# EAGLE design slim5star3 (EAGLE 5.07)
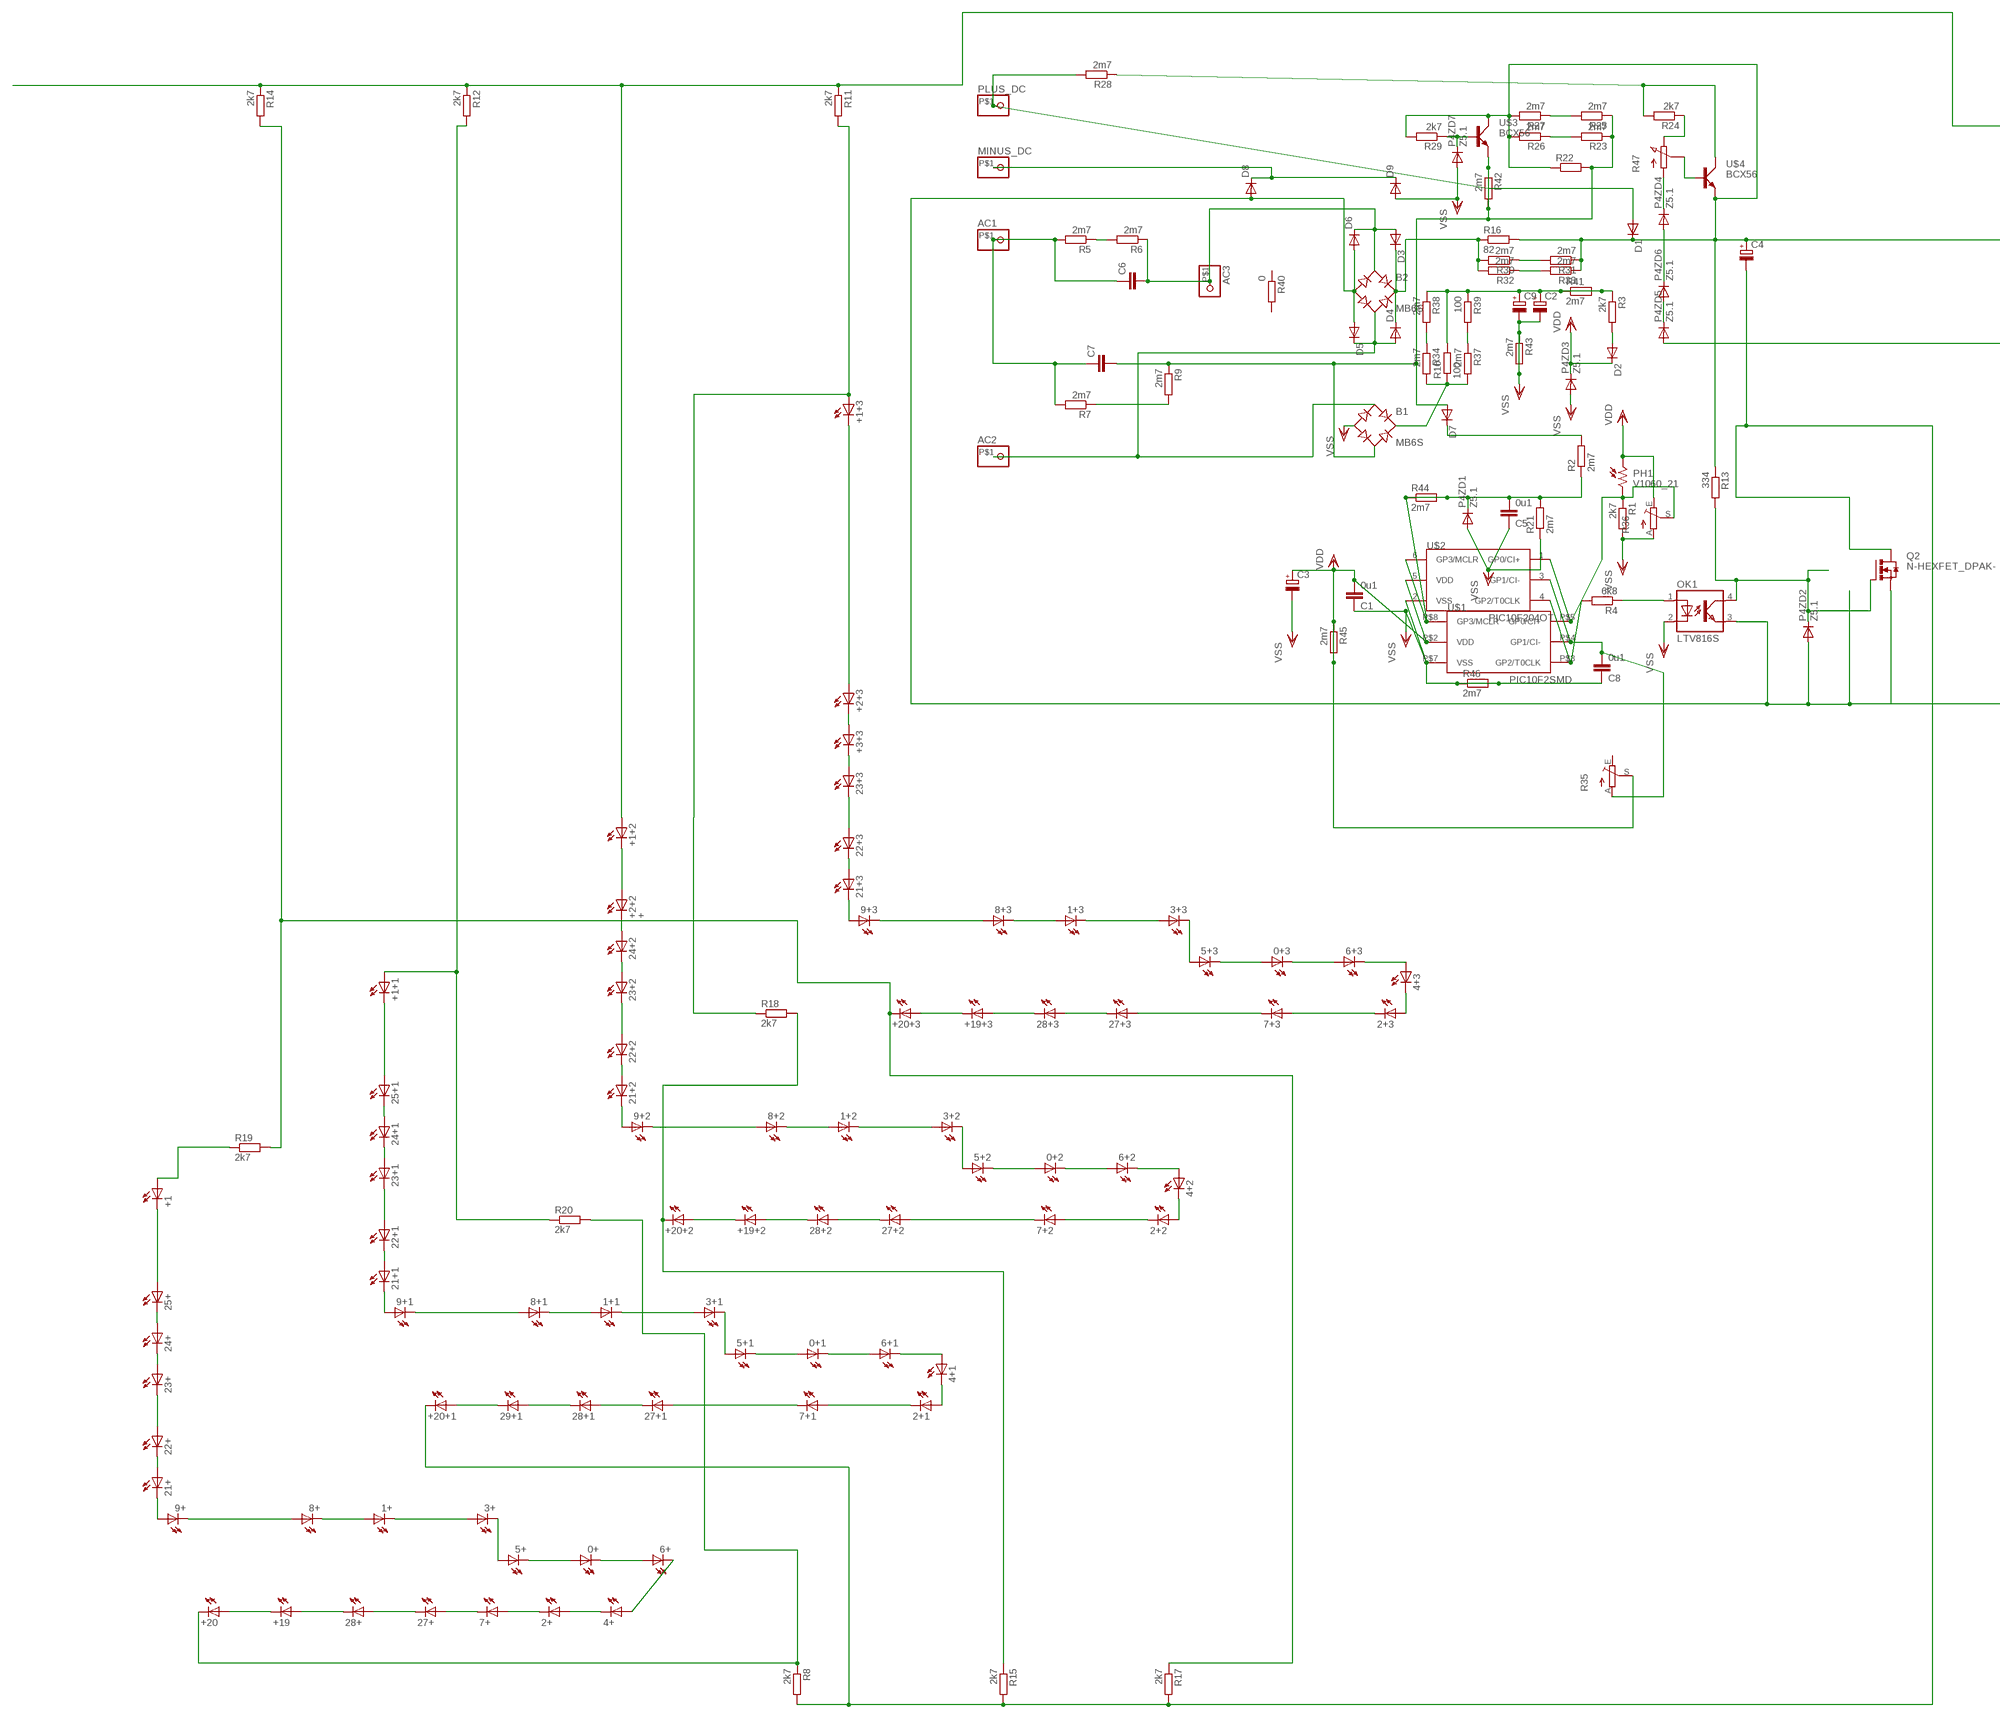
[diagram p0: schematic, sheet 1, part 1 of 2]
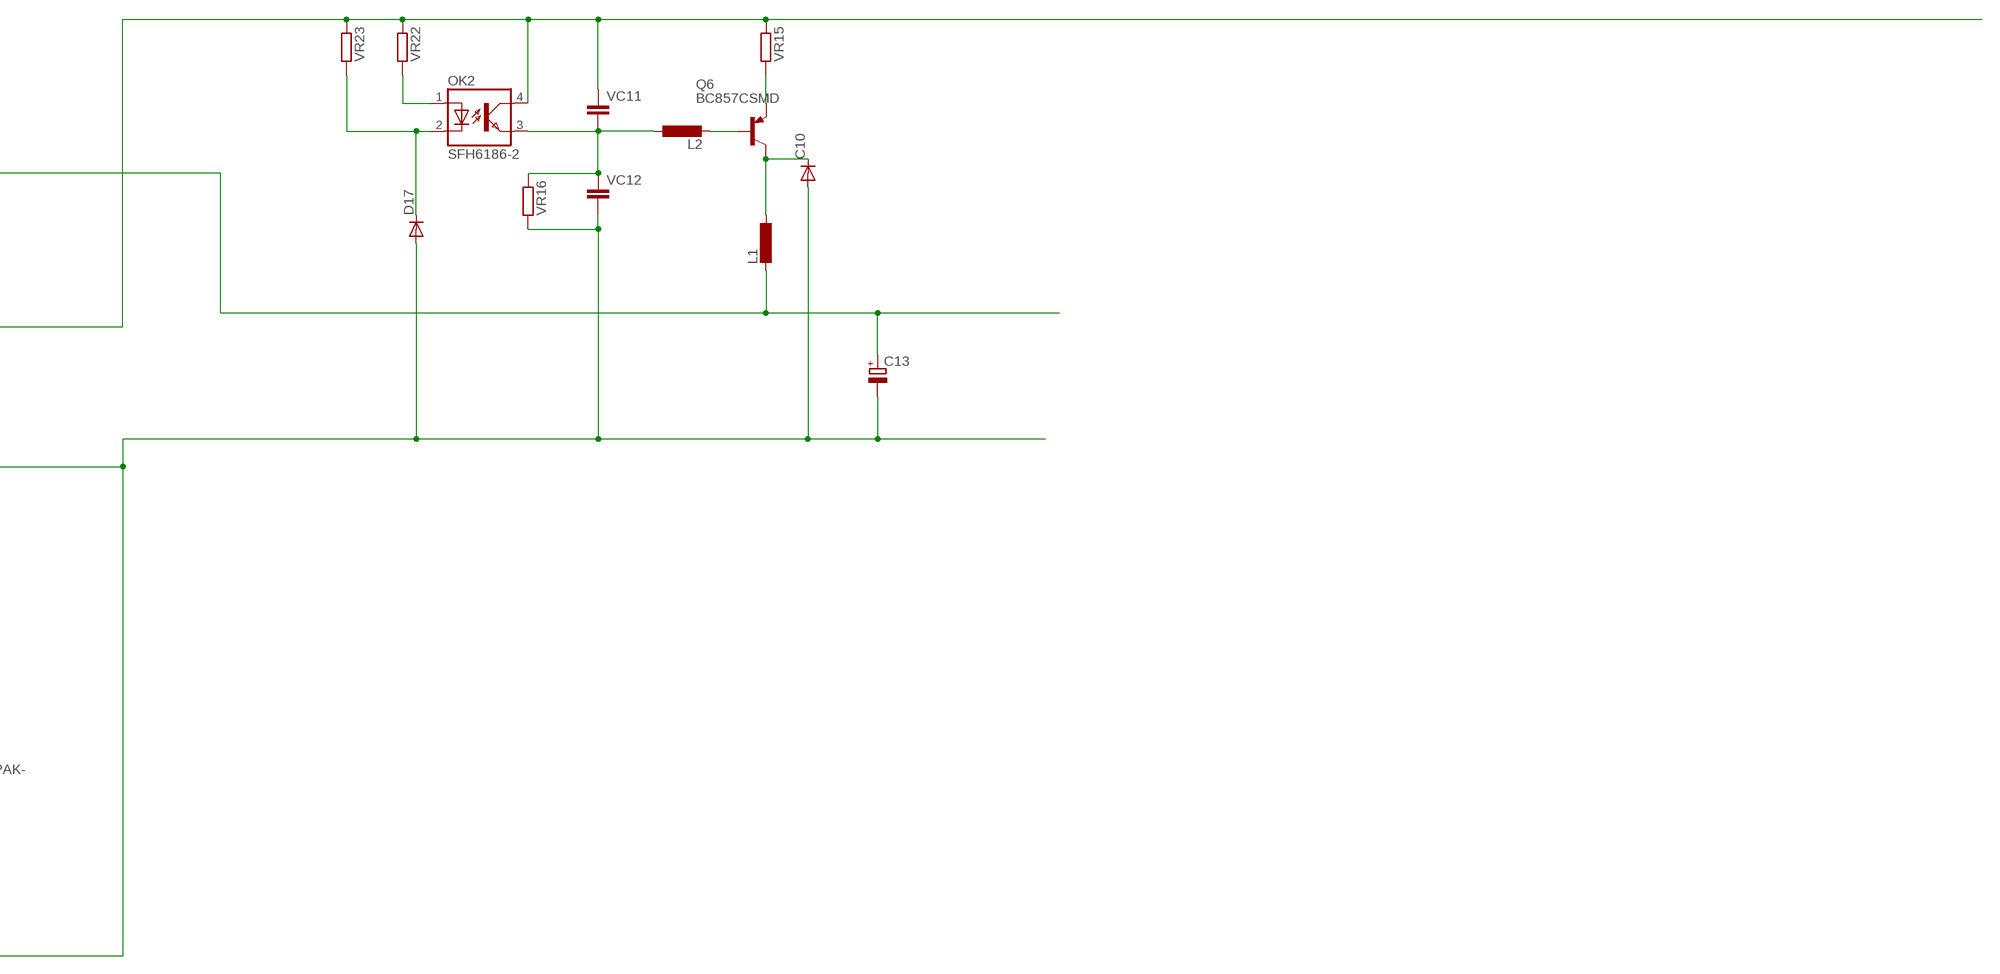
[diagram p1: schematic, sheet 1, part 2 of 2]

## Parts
0+  LED1210  [1210]
0+1  LED1210  [1210]
0+2  LED1210  [1210]
0+3  LED1210  [1210]
1+  LED1210  [1210]
1+1  LED1210  [1210]
1+2  LED1210  [1210]
1+3  LED1210  [1210]
2+  LED1210  [1210]
2+1  LED1210  [1210]
2+2  LED1210  [1210]
2+3  LED1210  [1210]
3+  LED1210  [1210]
3+1  LED1210  [1210]
3+2  LED1210  [1210]
3+3  LED1210  [1210]
4+  LED1210  [1210]
4+1  LED1210  [1210]
4+2  LED1210  [1210]
4+3  LED1210  [1210]
5+  LED1210  [1210]
5+1  LED1210  [1210]
5+2  LED1210  [1210]
5+3  LED1210  [1210]
6+  LED1210  [1210]
6+1  LED1210  [1210]
6+2  LED1210  [1210]
6+3  LED1210  [1210]
7+  LED1210  [1210]
7+1  LED1210  [1210]
7+2  LED1210  [1210]
7+3  LED1210  [1210]
8+  LED1210  [1210]
8+1  LED1210  [1210]
8+2  LED1210  [1210]
8+3  LED1210  [1210]
9+  LED1210  [1210]
9+1  LED1210  [1210]
9+2  LED1210  [1210]
9+3  LED1210  [1210]
21+  LED1210  [1210]
21+1  LED1210  [1210]
21+2  LED1210  [1210]
21+3  LED1210  [1210]
22+  LED1210  [1210]
22+1  LED1210  [1210]
22+2  LED1210  [1210]
22+3  LED1210  [1210]
23+  LED1210  [1210]
23+1  LED1210  [1210]
23+2  LED1210  [1210]
23+3  LED1210  [1210]
24+  LED1210  [1210]
24+1  LED1210  [1210]
24+2  LED1210  [1210]
25+  LED1210  [1210]
25+1  LED1210  [1210]
27+  LED1210  [1210]
27+1  LED1210  [1210]
27+2  LED1210  [1210]
27+3  LED1210  [1210]
28+  LED1210  [1210]
28+1  LED1210  [1210]
28+2  LED1210  [1210]
28+3  LED1210  [1210]
29+1  LED1210  [1210]
+1  LED1210  [1210]
+1+1  LED1210  [1210]
+1+2  LED1210  [1210]
+1+3  LED1210  [1210]
+2+2  +  LED1210  [1210]
+2+3  LED1210  [1210]
+3+3  LED1210  [1210]
+19  LED1210  [1210]
+19+2  LED1210  [1210]
+19+3  LED1210  [1210]
+20  LED1210  [1210]
+20+1  LED1210  [1210]
+20+2  LED1210  [1210]
+20+3  LED1210  [1210]
AC1  PINHD-1X1SMD  [SMD1X1]
AC2  PINHD-1X1SMD  [SMD1X1]
AC3  PINHD-1X1SMD  [SMD1X1]
B1  MB6S  [SOIC-4]
B2  MB6S  [SOIC-4]
C1  0u1  C-EUC1206  [C1206]
C2  CPOL-EUE2.5-4V  [E2,5RE]
C3  CPOL-EUE  [PANASONIC_E]
C4  CPOL-EUSANYO_SMD_F12  [SANYO-OSCON_SMD_F12]
C5  0u1  C-EUC1206  [C1206]
C6  C-EUSMD200  [SMD200]
C7  C-EUSMD100  [SMD100]
C8  0u1  C-EUC1206  [C1206]
C9  CPOL-EUE  [PANASONIC_E]
C10  DIODE-SMB  [SMB]
C13  CPOL-EUSMCC  [SMC_C]
D1  DIODE-SMB  [SMB]
D2  DIODE-MINIMELF  [MINIMELF]
D3  DIODE-SMB  [SMB]
D4  DIODE-SMB  [SMB]
D5  DIODE-SMB  [SMB]
D6  DIODE-SMB  [SMB]
D7  DIODE-MINIMELF  [MINIMELF]
D8  DIODE-SMB  [SMB]
D9  DIODE-SMB  [SMB]
D17  DIODE-MINIMELF  [MINIMELF]
L1  L-EUL5650M  [L5650M]
L2  L-EUL5650M  [L5650M]
MINUS_DC  PINHD-1X1SMD  [SMD1X1]
OK1  LTV816S  [SMD4]
OK2  SFH6186-2  [SMD4]
P4ZD1  Z5.1  DIODE-MINIMELF  [MINIMELF]
P4ZD2  Z5.1  DIODE-MINIMELF  [MINIMELF]
P4ZD3  Z5.1  DIODE-MINIMELF  [MINIMELF]
P4ZD4  Z5.1  DIODE-MINIMELF  [MINIMELF]
P4ZD5  Z5.1  DIODE-MINIMELF  [MINIMELF]
P4ZD6  Z5.1  DIODE-MINIMELF  [MINIMELF]
P4ZD7  Z5.1  DIODE-MINIMELF  [MINIMELF]
PH1  V1060_21  [TO-5_V10]
PLUS_DC  PINHD-1X1SMD  [SMD1X1]
Q2  N-HEXFET_DPAK-  [TO252]
Q6  BC857CSMD  [SOT23-BEC]
R1  2k7  R-EU_R1206  [R1206]
R2  2m7  R-EU_R2010  [R2010]
R3  2k7  R-EU_R1206  [R1206]
R4  6k8  R-EU_R1206  [R1206]
R5  2m7  R-EU_R1210  [R1210]
R6  2m7  R-EU_R1210  [R1210]
R7  2m7  R-EU_R1210  [R1210]
R8  2k7  R-EU_R0402  [R0402]
R9  2m7  R-EU_R1210  [R1210]
R10  100  R-EU_SMD15  [SMDCARB15]
R11  2k7  R-EU_R0402  [R0402]
R12  2k7  R-EU_R0402  [R0402]
R13  334  R-EU_R1206  [R1206]
R14  2k7  R-EU_R0402  [R0402]
R15  2k7  R-EU_R0402  [R0402]
R16  82  R-EU_SMD15  [SMDCARB15]
R17  2k7  R-EU_R0402  [R0402]
R18  2k7  R-EU_R0402  [R0402]
R19  2k7  R-EU_R0402  [R0402]
R20  2k7  R-EU_R0402  [R0402]
R21  2m7  R-EU_R1206  [R1206]
R22  R-EU_SMD15  [SMDCARB15]
R23  2m7  R-EU_R1210  [R1210]
R24  2k7  R-EU_R1206  [R1206]
R25  2m7  R-EU_R1210  [R1210]
R26  2m7  R-EU_R1210  [R1210]
R27  2m7  R-EU_R1210  [R1210]
R28  2m7  R-EU_R1210  [R1210]
R29  2k7  R-EU_R1206  [R1206]
R30  2m7  R-EU_R1210  [R1210]
R31  2m7  R-EU_R1210  [R1210]
R32  2m7  R-EU_R1210  [R1210]
R33  2m7  R-EU_R1210  [R1210]
R34  2m7  R-EU_R1210  [R1210]
R35  TRIM_EU-LI10  [LI10]
R36  TRIM_EU-LI15  [LI15]
R37  2m7  R-EU_R1210  [R1210]
R38  2m7  R-EU_R1210  [R1210]
R39  100  R-EU_R1210  [R1210]
R40  0  R-EU_R2010  [R2010]
R41  2m7  R-EU_R2010  [R2010]
R42  2m7  R-EU_R2010  [R2010]
R43  2m7  R-EU_R2010  [R2010]
R44  2m7  R-EU_R2010  [R2010]
R45  2m7  R-EU_R2010  [R2010]
R46  2m7  R-EU_R2010  [R2010]
R47  PC25  [PC25]
U$1  PIC10F2SMD  [DIL8SMD]
U$2  PIC10F204OT  [SOT23-6]
U$3  BCX56  [SOT223]
U$4  BCX56  [SOT223]
VC11  C-EUC0805  [C0805]
VC12  C-EUC0805  [C0805]
VR15  R-EU_R1210  [R1210]
VR16  R-EU_R1206  [R1206]
VR22  R-EU_R1206  [R1206]
VR23  R-EU_R1206  [R1206]

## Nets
AC1: AC1.P$1 C6.P$1 C7.P$1 R5.2 R7.2
AC2: AC2.P$1 B1.~1(AC1) B2.~2(AC2) D4.A D5.C
BATT-: B2.- C10.A C13.- D5.A D6.A D8.A D17.A OK1.3(EMIT) P4ZD2.A P4ZD5.A Q2.2(S) VC12.2 VR16.2
CBIG: AC3.P$1 B2.~1(AC1) C6.P$2 D3.A D6.C R6.1
CSMALL: B1.~2(AC2) C7.P$2 D7.A R9.1 R22.P$2 R23.1 R25.1 R42.1 R42.2 U$3.1(E)
D+: +1+2.P$1(A) C13.+ L1.2 R11.1 R12.1 R14.1
MI-: D8.C D9.C MINUS_DC.P$1
MINUS: +20+1.P$2(C) C4.- Q2.3(D) R8.2 R15.2 R17.2
N$1: +1+3.P$1(A) R11.2 R18.1
N$2: +1+1.P$1(A) R12.2 R20.1
N$4: +1.P$1(A) R19.1
N$5: D7.C R2.2
N$6: 8+.P$1(A) 9+.P$2(C)
N$7: +19.P$2(C) +20.P$1(A)
N$8: 28+.P$2(C) +19.P$1(A)
N$9: 27+.P$2(C) 28+.P$1(A)
N$10: 29+1.P$2(C) +20+1.P$1(A)
N$11: 28+1.P$2(C) 29+1.P$1(A)
N$12: 2+.P$2(C) 7+.P$1(A)
N$13: 7+.P$2(C) 27+.P$1(A)
N$14: 2+.P$1(A) 4+.P$2(C)
N$15: 4+.P$1(A) 6+.P$2(C)
N$16: 0+.P$2(C) 6+.P$1(A)
N$17: 0+.P$1(A) 5+.P$2(C)
N$18: 3+.P$2(C) 5+.P$1(A)
N$19: 1+.P$2(C) 3+.P$1(A)
N$20: 1+.P$1(A) 8+.P$2(C)
N$21: 27+1.P$2(C) 28+1.P$1(A)
N$22: 2+1.P$1(A) 4+1.P$2(C)
N$23: 9+.P$1(A) 21+.P$2(C)
N$24: 21+.P$1(A) 22+.P$2(C)
N$25: 22+.P$1(A) 23+.P$2(C)
N$26: 24+.P$1(A) 25+.P$2(C)
N$27: 25+.P$1(A) +1.P$2(C)
N$28: 23+.P$1(A) 24+.P$2(C)
N$29: 4+1.P$1(A) 6+1.P$2(C)
N$30: 0+1.P$2(C) 6+1.P$1(A)
N$31: 0+1.P$1(A) 5+1.P$2(C)
N$32: 3+1.P$2(C) 5+1.P$1(A)
N$33: 1+1.P$2(C) 3+1.P$1(A)
N$34: 1+1.P$1(A) 8+1.P$2(C)
N$35: 9+1.P$1(A) 21+1.P$2(C)
N$36: 21+1.P$1(A) 22+1.P$2(C)
N$37: 22+1.P$1(A) 23+1.P$2(C)
N$38: 25+1.P$1(A) +1+1.P$2(C)
N$39: 24+1.P$1(A) 25+1.P$2(C)
N$40: 23+1.P$1(A) 24+1.P$2(C)
N$41: 2+1.P$2(C) 7+1.P$1(A)
N$42: 7+1.P$2(C) 27+1.P$1(A)
N$43: 8+1.P$1(A) 9+1.P$2(C)
N$45: +20+3.P$2(C) R14.2 R17.1 R19.2
N$46: +19+2.P$2(C) +20+2.P$1(A)
N$47: 28+2.P$2(C) +19+2.P$1(A)
N$48: 27+2.P$2(C) 28+2.P$1(A)
N$49: 2+2.P$1(A) 4+2.P$2(C)
N$50: 4+2.P$1(A) 6+2.P$2(C)
N$51: 0+2.P$2(C) 6+2.P$1(A)
N$52: 0+2.P$1(A) 5+2.P$2(C)
N$53: 3+2.P$2(C) 5+2.P$1(A)
N$54: 1+2.P$2(C) 3+2.P$1(A)
N$55: 1+2.P$1(A) 8+2.P$2(C)
N$56: 9+2.P$1(A) 21+2.P$2(C)
N$57: 21+2.P$1(A) 22+2.P$2(C)
N$58: 22+2.P$1(A) 23+2.P$2(C)
N$59: +1+2.P$2(C) +2+2.P$1(A)
N$60: 24+2.P$1(A) +2+2.P$2(C)
N$61: 23+2.P$1(A) 24+2.P$2(C)
N$62: 2+2.P$2(C) 7+2.P$1(A)
N$63: 7+2.P$2(C) 27+2.P$1(A)
N$64: 8+2.P$1(A) 9+2.P$2(C)
N$65: +20+2.P$2(C) R15.1 R18.2
N$66: +20.P$2(C) R8.1 R20.2
N$67: +19+3.P$2(C) +20+3.P$1(A)
N$68: 28+3.P$2(C) +19+3.P$1(A)
N$69: 27+3.P$2(C) 28+3.P$1(A)
N$70: 2+3.P$1(A) 4+3.P$2(C)
N$71: 4+3.P$1(A) 6+3.P$2(C)
N$72: 0+3.P$2(C) 6+3.P$1(A)
N$73: 0+3.P$1(A) 5+3.P$2(C)
N$74: 3+3.P$2(C) 5+3.P$1(A)
N$75: 1+3.P$2(C) 3+3.P$1(A)
N$76: 1+3.P$1(A) 8+3.P$2(C)
N$77: 9+3.P$1(A) 21+3.P$2(C)
N$78: 21+3.P$1(A) 22+3.P$2(C)
N$79: 22+3.P$1(A) 23+3.P$2(C)
N$80: +1+3.P$2(C) +2+3.P$1(A)
N$81: +2+3.P$2(C) +3+3.P$1(A)
N$82: 23+3.P$1(A) +3+3.P$2(C)
N$83: 2+3.P$2(C) 7+3.P$1(A)
N$84: 7+3.P$2(C) 27+3.P$1(A)
N$85: 8+3.P$1(A) 9+3.P$2(C)
N$86: C5.2 P4ZD1.C R2.1 R21.2 R44.1 R44.2 U$1.P$8(GP3/MCLR) U$2.6(GP3/MCLR)
N$87: OK1.1(A) R4.1
N$88: PH1.2 R1.1 R36.S U$1.P$5(GP0/CI+) U$2.1(GP0/CI+)
N$89: R5.1 R6.2
N$90: R7.1 R9.2
N$91: B2.+ D3.C D4.C R16.P$1 R30.2 R32.2
N$92: D2.A R3.2
N$94: OK1.4(COL) P4ZD2.C Q2.1(G) R13.2
N$95: R4.2 U$1.P$3(GP2/T0CLK) U$2.4(GP2/T0CLK)
N$96: R24.2 R28.1 U$4.2(C)
N$97: R47.S U$4.3(B)
N$98: D1.A PLUS_DC.P$1 R28.2
N$99: R23.2 R26.1
N$100: R25.2 R27.1
N$101: C2.+ C9.+ R3.1 R10.P$2 R38.1 R39.1 R41.1 R41.2
N$102: C8.2 R35.A U$1.P$4(GP1/CI-) U$2.3(GP1/CI-)
N$103: P4ZD5.C P4ZD6.A
N$104: P4ZD7.C R29.1 U$3.3(B)
N$105: P4ZD4.A P4ZD6.C
N$106: Q6.E VR15.2
N$107: R30.1 R31.2
N$108: R32.1 R33.2
N$109: B1.+ R10.P$1 R34.2 R37.2
N$110: R34.1 R38.2
N$111: R37.1 R39.2
N$112: P4ZD4.C R47.A
N$113: R24.1 R47.E
N$114: L2.2 Q6.B
N$115: C10.C L1.1 Q6.C
N$116: L2.1 OK2.3(EMIT) VC11.2 VC12.1 VR16.1
N$117: D17.C OK2.2(C) VR23.2
N$118: OK2.1(A) VR22.2
PLUS5: C4.+ D1.C OK2.4(COL) R13.1 R16.P$2 R22.P$1 R26.2 R27.2 R29.2 R31.1 R33.1 U$3.2(C) U$4.1(E) VC11.1 VR15.1 VR22.1 VR23.1
VDD: C1.2 C3.+ D2.C P4ZD3.C PH1.1 R35.S R36.E R45.1 R45.2 U$1.P$2(VDD) U$2.5(VDD)
VSS: B1.- C1.1 C2.- C3.- C5.1 C8.1 C9.- D9.A OK1.2(C) P4ZD1.A P4ZD3.A P4ZD7.A R1.2 R21.1 R36.A R43.1 R43.2 R46.1 R46.2 U$1.P$7(VSS) U$2.2(VSS)
Unconnected: R35.E R40.1 R40.2

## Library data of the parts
0+ 0+1-0+3 1+ 1+1-1+3 2+ 2+1-2+3 3+ 3+1-3+3 4+ 4+1-4+3 5+ 5+1-5+3 6+ 6+1-6+3 7+ 7+1-7+3 8+ 8+1-8+3 9+ 9+1-9+3 21+ 21+1-21+3 22+ 22+1-22+3 23+ 23+1-23+3 24+ 24+1 24+2 25+ 25+1 27+ 27+1-27+3 28+ 28+1-28+3 29+1 +1 +1+1-+1+3 +2+2 +2+3 +3+3 +19 +19+2 +19+3 +20 +20+1-+20+3 = led(2):LED: LED
AC1-AC3 MINUS_DC PLUS_DC = pinhead:PINHD-1X1: PIN HEADER
B1 B2 = rectifier:MB*S: Bridge Rectifier Source: http://www.fairchildsemi.com/ds/MB/MB6S.pdf
C1 C5-C8 VC11 VC12 = rcl:C-EU: CAPACITOR, European symbol
C2-C4 C9 = rcl-2:CPOL-EU: POLARIZED CAPACITOR, European symbol
C10 D1-D9 D17 P4ZD1-P4ZD7 = diode:DIODE-: DIODE
C13 = rcl:CPOL-EU: POLARIZED CAPACITOR, European symbol
L1 L2 = rcl:L-EU: INDUCTOR, European symbol
OK1 = optocoupler:LTV816: OPTO COUPLER Source: LITEON, LTV816.pdf
OK2 = optocoupler:SFH618?*: Optocoupler, Phototransistor Output, Low Input Current Source: http://www.vishay.com/docs/83673/sfh618.pdf
PH1 = photo-elements:?1060*: Sensor Street Light control
Q2 = transistor-power:N-HEXFET_?-*: HEXFET® Power MOSFET
Q6 = transistor-pnp:BC857*: PNP Transistror
R1-R9 R11-R15 R17-R21 R23-R34 R37-R46 VR15 VR16 VR22 VR23 = rcl-2:R-EU_: RESISTOR, European symbol
R10 R16 R22 = rcl:R-EU_: RESISTOR, European symbol
R35 R36 = pot:TRIM_EU-: POTENTIOMETER
R47 = pot-vitrohm:PC25: VITROHM POTENTIOMETER
U$1 U$2 = microchip-5:PIC10F2*: uPC nW 0,25/0,5k Program Flash memory Comparator
U$3 U$4 = transistor-power:BCX56

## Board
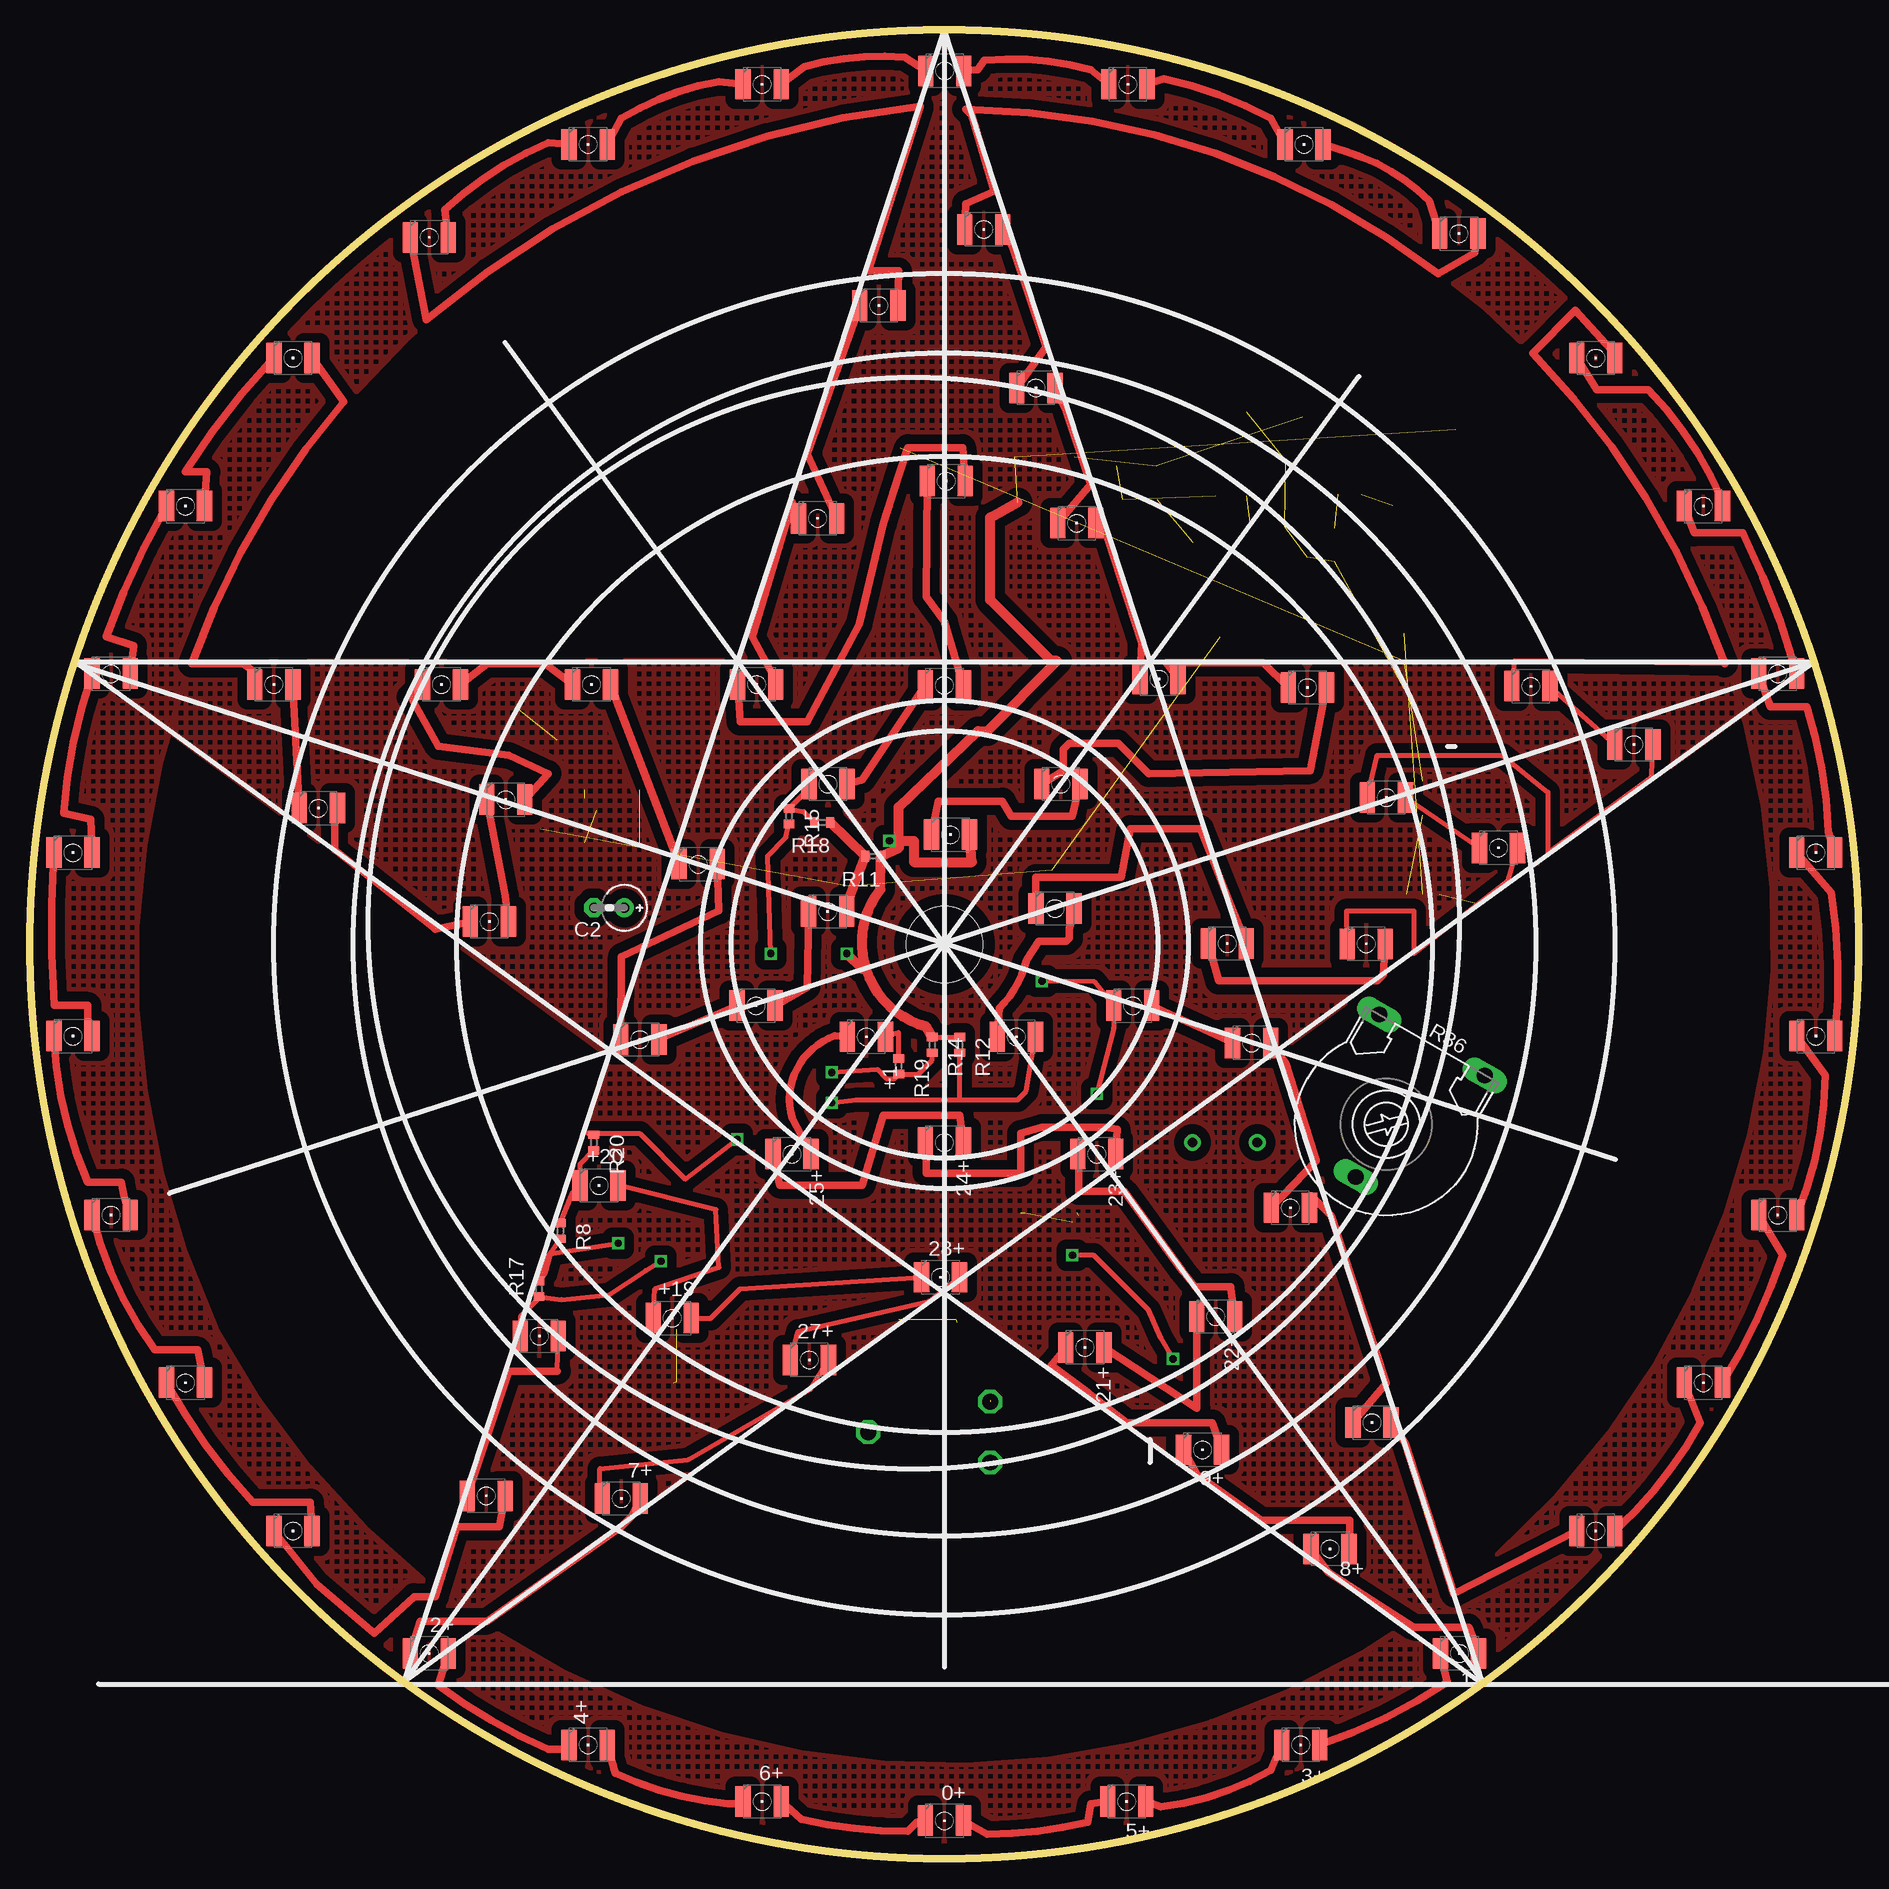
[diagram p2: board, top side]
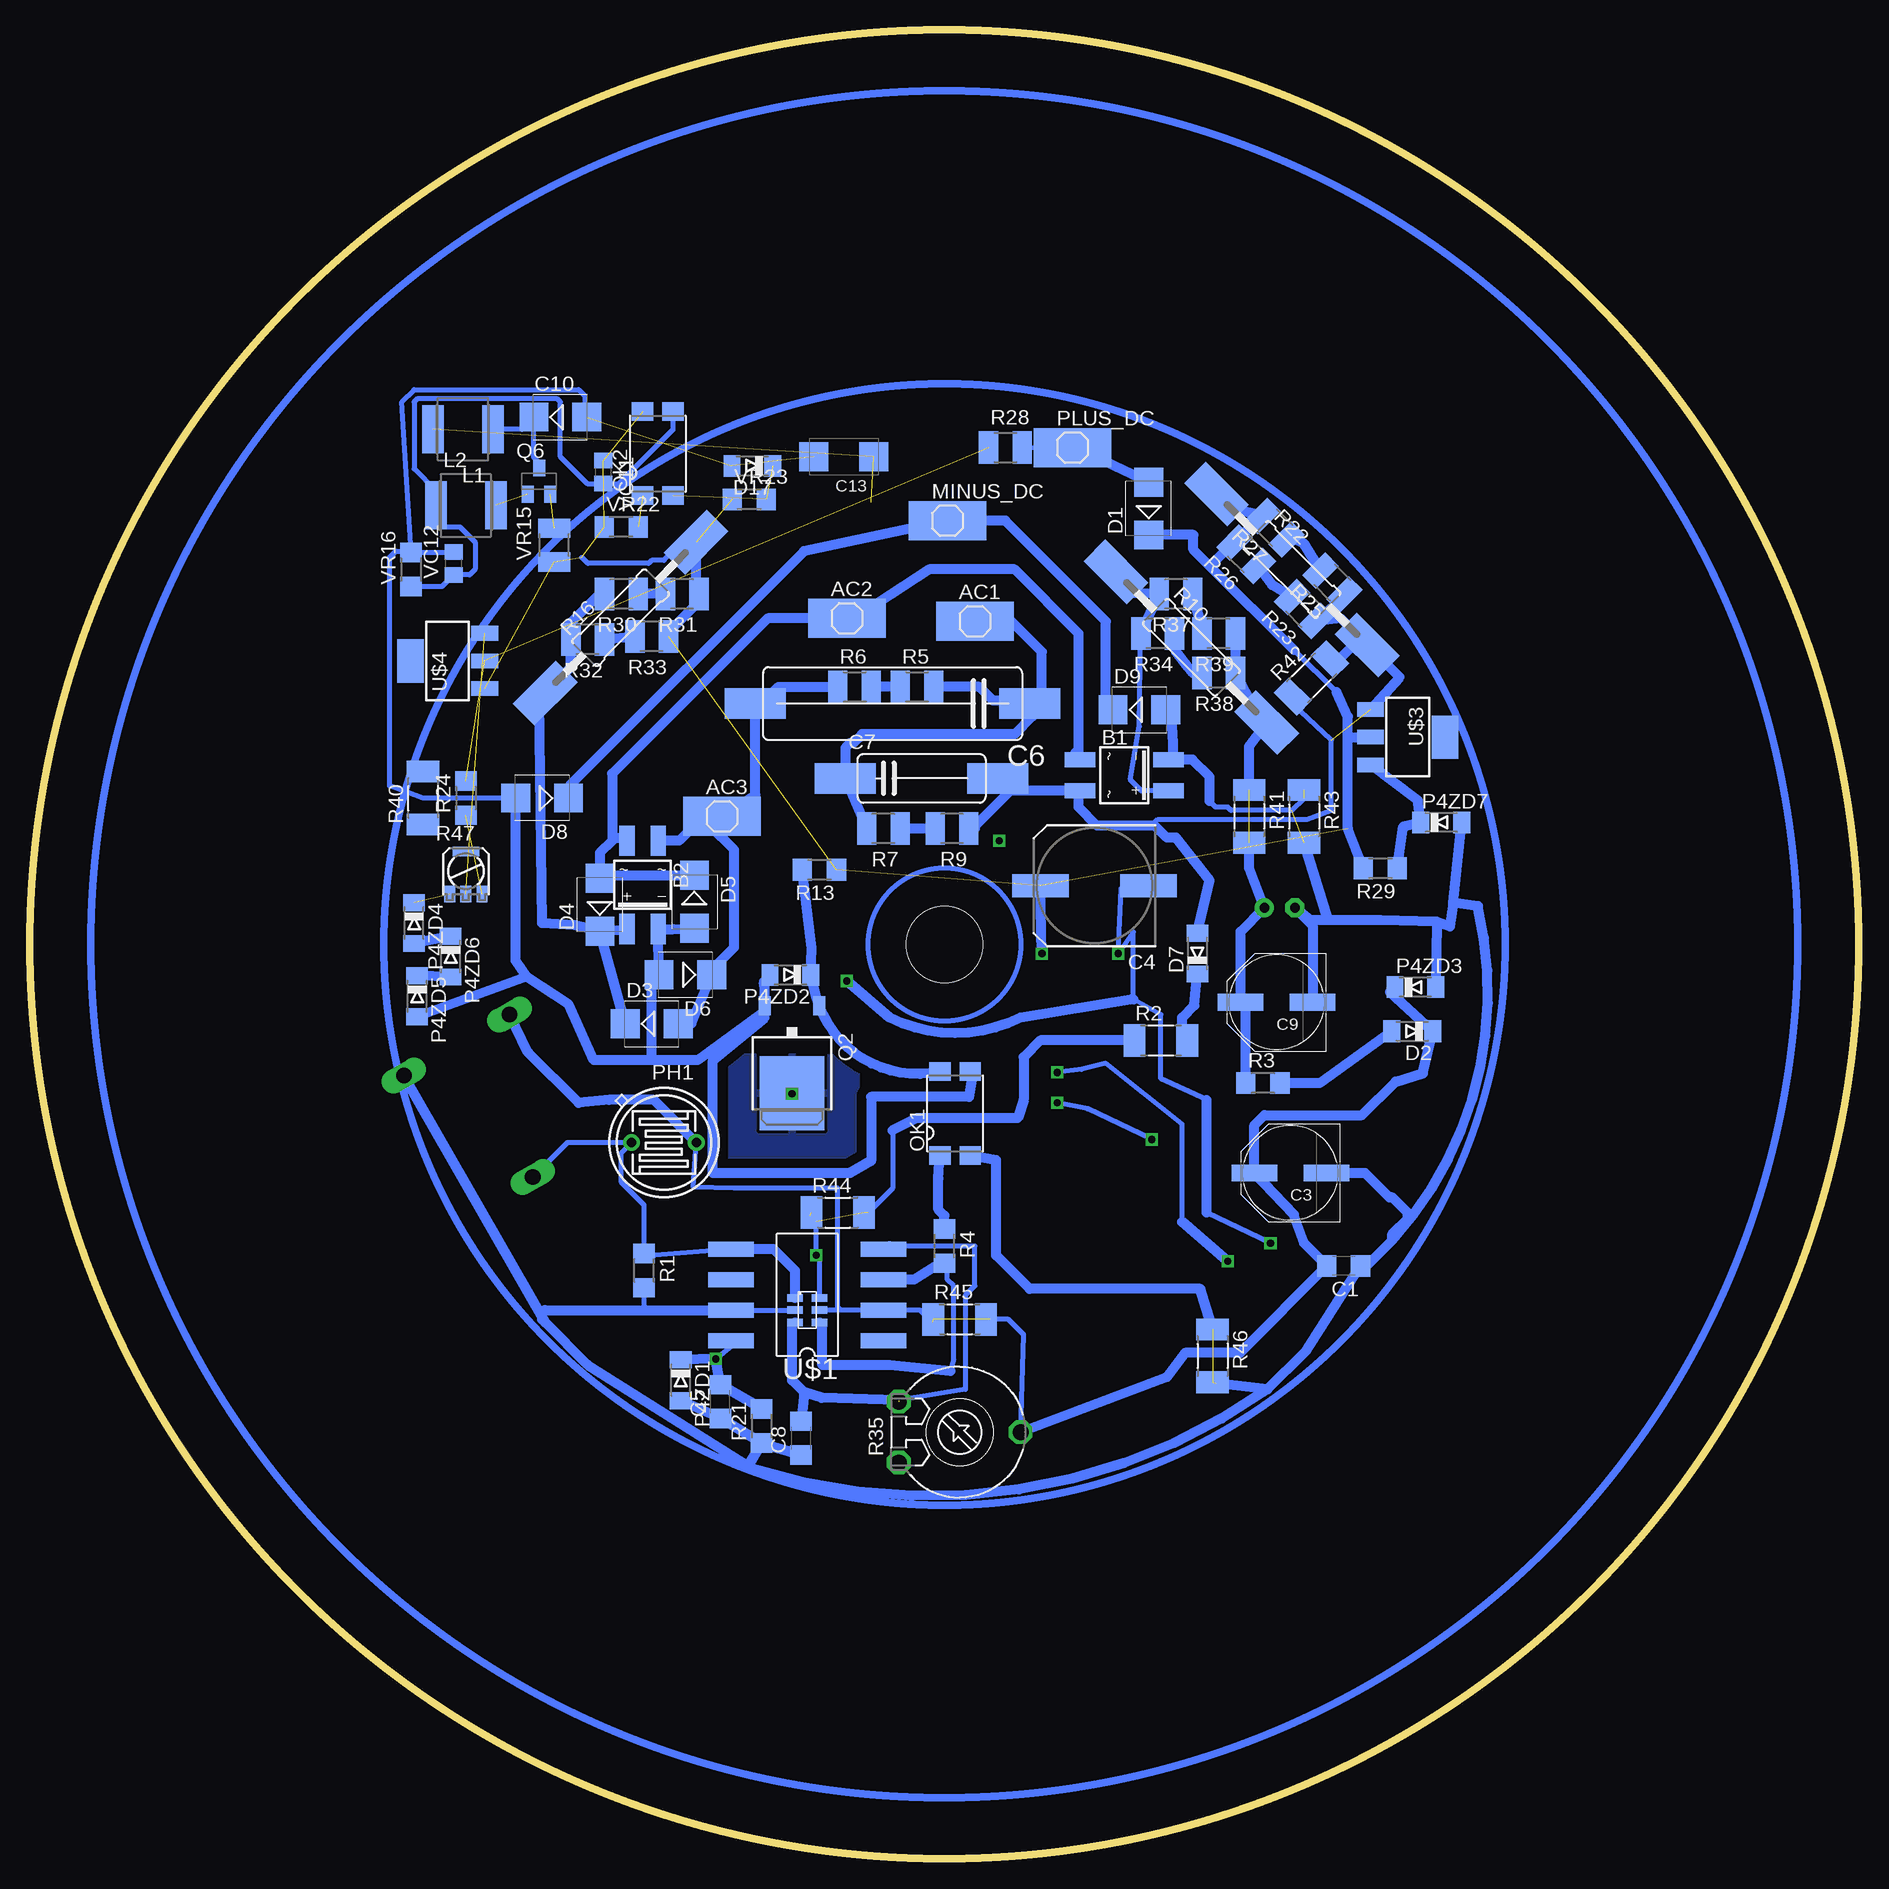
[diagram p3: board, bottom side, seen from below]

Size 152.4 x 152.4 mm. Coordinates in mm from the lower left corner, seen from the top.
Outline: circle at 76.2,76.2 radius 76.2
Copper layers (1*16): Top 0.035mm / dielectric 1.5mm / Bottom 0.035mm
Design rules "default": minimum track width 10mil, minimum drill 24mil, track to track 8mil, track to pad 8mil, pad to pad 8mil, via to via 8mil, smd to smd 8mil, copper to edge 40mil, drill to drill 8mil, minimum pad ring 10mil, minimum via ring 8mil, stop-mask expansion 4mil, vias tented up to drill 0mil, thermal gap 10mil
Holes 6.35 mm at 76.2,76.2

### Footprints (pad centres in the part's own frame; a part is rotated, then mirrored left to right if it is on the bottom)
1210 = smd 1.27 x 2.54: P$1 1.587,0; P$2 -1.587,0
SMD1X1 = smd 6.452 x 3.251: P$1 0,0
SOIC-4 = smd 1.27 x 2.54: + 1.3,3.685; - -1.3,3.685; ~1 -1.3,-3.685; ~2 1.3,-3.685
C1206 = smd 1.6 x 1.8: 1 -1.4,0; 2 1.4,0
E2,5RE = drill 0.813 pad 1.575 round: + -1.27,0 | drill 0.813 pad 1.575 octagon: - 1.27,0
PANASONIC_E = smd 3.8 x 1.4: + 3,0; - -3,0
SANYO-OSCON_SMD_F12 = smd 4.7 x 1.9: + 4.5,0; - -4.5,0
SMD200 = smd 5.08 x 2.54: P$1 -10.16,0; P$2 12.7,0
SMD100 = smd 5.08 x 2.54: P$1 -6.35,0; P$2 6.35,0
SMB = smd 2.4 x 2.4: A 2.2,0; C -2.2,0
SMC_C = smd 2.4 x 2.4: + -2.5,0; - 2.5,0
MINIMELF = smd 1.4 x 1.8: A 1.7,0; C -1.7,0
L5650M = smd 1.8 x 4: 1 -2.5,0; 2 2.5,0
SMD4 = smd 1.78 x 1.55: 1 -1.27,-3.5; 2 1.27,-3.5; 3 1.27,3.5; 4 -1.27,3.5
TO-5_V10 = drill 0.8 pad 1.4 round: 1 -2.7,0; 2 2.7,0
TO252 = smd 1 x 1.6: 1 -2.28,-3.53; 2 2.28,-3.53 | smd 5.4 x 6.2: 3 0,3.77
SOT23-BEC = smd 1 x 1.4: B -0.95,-1.1; C 0,1.1; E 0.95,-1.1
R1206 = smd 1.6 x 1.803: 1 -1.422,0; 2 1.422,0
R2010 = smd 1.8 x 2.7: 1 -2.2,0; 2 2.2,0
R1210 = smd 1.6 x 2.7: 1 -1.4,0; 2 1.4,0
R0402 = smd 0.7 x 0.9: 1 -0.65,0; 2 0.65,0
SMDCARB15 = smd 5.08 x 2.54: P$1 -8.89,0; P$2 8.89,0
LI10 = drill 1.321 octagon: A -2.54,-5.08; E 2.54,-5.08; S 0,5.08
LI15 = drill 1.321 long: A -5.08,-7.62; E 5.08,-7.62; S 0,5.08
PC25 = smd 2.2 x 0.8: 4 0,1.65 | smd 0.9 x 1.4: A -1.35,-1.9; E 1.35,-1.9; S 0,-1.9
DIL8SMD = smd 1.27 x 3.81: P$1 -3.81,-6.35; P$2 -1.27,-6.35; P$3 1.27,-6.35; P$4 3.81,-6.35; P$5 3.81,6.35; P$6 1.27,6.35; P$7 -1.27,6.35; P$8 -3.81,6.35
SOT23-6 = smd 0.635 x 1.27: 1 -1.016,-1.016; 2 0,-1.016; 3 1.016,-1.016; 4 1.016,1.016; 5 0,1.016; 6 -1.016,1.016
SOT223 = smd 1.219 x 2.235: 1 -2.311,-3.099; 2 0,-3.099; 3 2.311,-3.099 | smd 3.6 x 2.2: 4 0,3.099
C0805 = smd 1.3 x 1.5: 1 -0.95,0; 2 0.95,0

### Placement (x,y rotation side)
0+  76.2,3.17 0 top
0+1  148.82,83.85 0 top
0+2  61.01,147.88 0 top
0+3  12.95,112.73 0 top
1+  119.13,17.12 0 top
1+1  130.48,125.07 0 top
1+2  106.17,142.88 0 top
1+3  24.03,87.55 0 top
2+  33.27,17.12 0 top
2+1  139.45,39.67 0 top
2+2  70.74,129.44 0 top
2+3  3.58,68.55 0 top
3+  105.89,9.5 0 top
3+1  139.45,112.73 0 top
3+2  91.49,147.88 0 top
3+3  20.32,97.87 0 top
4+  46.51,9.5 0 top
4+1  145.64,53.64 0 top
4+2  33.27,135.13 0 top
4+3  3.58,83.85 0 top
5+  91.39,4.78 0 top
5+1  145.64,98.76 0 top
5+2  76.23,149 0 top
5+3  21.92,125.07 0 top
6+  61.01,4.78 0 top
6+1  148.82,68.55 0 top
6+2  46.51,142.88 0 top
6+3  6.76,98.76 0 top
7+  49.28,30.02 0 top
7+1  130.48,27.33 0 top
7+2  65.63,111.71 0 top
7+3  6.76,53.64 0 top
8+  108.33,25.83 0 top
8+1  125.07,97.71 0 top
8+2  119.08,135.43 0 top
8+3  38.28,78.11 0 top
9+  97.71,34.09 0 top
9+1  133.65,92.86 0 top
9+2  79.48,135.79 0 top
9+3  39.65,88.27 0 top
21+  87.91,42.62 0 top
21+1  113.03,88.44 0 top
21+2  83.82,122.58 0 top
21+3  34.29,97.87 0 top
22+  98.81,45.19 0 top
22+1  122.38,84.25 0 top
22+2  87.22,111.3 0 top
22+3  46.79,97.87 0 top
23+  88.9,58.72 0 top
23+1  111.35,76.25 0 top
23+2  94.08,98.32 0 top
23+3  55.68,82.88 0 top
24+  76.2,59.69 0 top
24+1  99.77,76.28 0 top
24+2  106.45,97.61 0 top
25+  63.5,58.72 0 top
25+1  85.42,79.2 0 top
27+  64.95,41.58 0 top
27+1  111.84,36.35 0 top
27+2  60.55,97.87 0 top
27+3  12.95,39.67 0 top
28+  75.87,48.46 0 top
28+1  105.03,54.25 0 top
28+2  76.35,114.81 0 top
28+3  21.92,27.33 0 top
29+1  101.8,68 0 top
+1  69.7,68.5 0 top
+1+1  82.19,68.5 0 top
+1+2  76.71,85.34 0 top
+1+3  66.47,78.94 0 top
+2+2  85.9,89.56 0 top
+2+3  60.5,71.09 0 top
+3+3  50.83,68.28 0 top
+19  53.52,45.06 0 top
+19+2  76.2,97.79 0 top
+19+3  38.02,30.25 0 top
+20  47.42,56.11 0 top
+20+1  91.9,71.09 0 top
+20+2  66.5,89.56 0 top
+20+3  42.44,43.56 0 top
AC1  73.66,103.12 0 bottom
AC2  84.33,103.38 0 bottom
AC3  94.74,86.87 0 bottom
B1  61.21,90.3 270 bottom
B2  101.35,81.15 180 bottom
C1  42.93,49.4 180 bottom
C2  48.26,79.25 180 top
C3  47.37,57.15 180 bottom
C4  63.7,81.09 180 bottom
C5  94.87,38.1 90 bottom
C6  79.25,96.27 180 bottom
C7  78.11,90.04 0 bottom
C8  88.14,35.05 90 bottom
C9  48.51,71.37 180 bottom
C10  108.2,120.14 0 bottom
C13  84.58,116.84 180 bottom
D1  59.18,112.52 90 bottom
D2  37.21,68.96 180 bottom
D3  100.58,69.6 0 bottom
D4  104.9,79.5 90 bottom
D5  97.03,79.76 270 bottom
D6  97.79,73.66 180 bottom
D7  55.12,75.44 90 bottom
D8  109.73,88.39 180 bottom
D9  59.94,95.76 0 bottom
D17  92.2,116.08 180 bottom
L1  116.33,119.13 180 bottom
L2  116.08,112.78 0 bottom
MINUS_DC  75.95,111.51 0 bottom
OK1  75.31,62.1 0 bottom
OK2  100.08,117.09 0 bottom
P4ZD1  98.17,39.88 270 bottom
P4ZD2  89.03,73.66 180 bottom
P4ZD3  36.96,72.64 0 bottom
P4ZD4  120.4,77.98 270 bottom
P4ZD5  120.14,71.88 270 bottom
P4ZD6  117.35,75.18 270 bottom
P4ZD7  34.8,86.36 0 bottom
PH1  99.57,59.69 180 bottom
PLUS_DC  65.53,117.6 0 bottom
Q2  88.9,67.56 180 bottom
Q6  109.98,114.81 0 bottom
R1  101.22,49.02 270 bottom
R2  58.17,68.2 0 bottom
R3  49.66,64.64 0 bottom
R4  76.2,51.05 270 bottom
R5  78.49,97.66 0 bottom
R6  83.69,97.66 0 bottom
R7  81.28,85.85 180 bottom
R8  44.2,52.32 270 top
R9  75.56,85.85 180 bottom
R10  55.63,100.97 315 bottom
R11  70.26,83.55 180 top
R12  77.47,67.82 270 top
R13  86.61,82.42 180 bottom
R14  75.18,67.82 270 top
R15  63.25,86.87 270 top
R16  103.18,103.43 45 bottom
R17  42.42,47.5 90 top
R18  66.04,86.36 180 top
R19  72.39,66.04 270 top
R20  46.99,59.69 270 top
R21  91.44,36.07 90 bottom
R22  47.24,107.44 315 bottom
R23  46.23,104.14 135 bottom
R24  116.08,88.39 90 bottom
R25  43.87,106.35 135 bottom
R26  51.05,108.71 135 bottom
R27  48.69,110.92 135 bottom
R28  71.12,117.6 0 bottom
R29  39.88,82.55 180 bottom
R30  103.12,105.41 180 bottom
R31  98.04,105.41 180 bottom
R32  105.92,101.6 180 bottom
R33  100.58,101.85 180 bottom
R34  58.42,102.11 180 bottom
R35  74.93,35.56 270 bottom
R36  113.03,61.21 150 top
R37  56.9,105.41 180 bottom
R38  53.34,98.81 180 bottom
R39  53.34,102.11 180 bottom
R40  119.63,88.39 90 bottom
R41  50.8,86.87 270 bottom
R42  45.61,98.4 45 bottom
R43  46.23,86.87 270 bottom
R44  85.09,53.85 0 bottom
R45  74.93,44.96 0 bottom
R46  53.85,41.91 270 bottom
R47  116.08,82.3 0 bottom
U$1  87.63,46.99 90 bottom
U$2  87.63,45.72 270 bottom
U$3  37.59,93.47 270 bottom
U$4  117.6,99.82 90 bottom
VC11  104.65,115.57 270 bottom
VC12  117.09,107.95 90 bottom
VR15  108.71,109.47 90 bottom
VR16  120.65,107.44 90 bottom
VR22  103.12,111 0 bottom
VR23  92.46,113.28 0 bottom

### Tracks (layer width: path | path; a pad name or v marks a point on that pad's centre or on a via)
AC1
  Bottom 0.813: R7.2 C7.P$1 84.45,92.58 84.07,92.96 83.82,92.96 83.06,93.73 70.36,93.73 68.83,95.25 68.83,96.01 C6.P$1 | AC1.P$1 70.61,103.12 68.07,100.58 68.07,97.28 C6.P$1 | R5.2 73.28,97.66 72.14,96.52 69.34,96.52 C6.P$1
AC2
  Bottom 0.813: 103.89,84.84 103.63,85.09 102.9,85.09 B2.~2 | D5.C 103.89,81.96 D4.A 104.9,83.82 103.89,84.84 | 103.89,84.84 103.89,90.42 90.93,103.38 AC2.P$1 81.79,104.65 77.47,107.44 70.36,107.44 65.02,102.11 65.02,92.2 65.28,92.2 65.28,91.98 B1.~1
BATT-  (2 unrouted)
  Bottom 0.406: VR16.2 121.41,121.41 120.4,122.43 106.68,122.43 106.17,121.92 106.17,120.31 C10.A | D8.A 119.63,88.39 122.43,89.41 122.43,108.46 121.92,108.97 120.75,108.97 VR16.2 | VR16.2 117.13,108.86 VC12.2
  Bottom 0.813: 111,73.48 107.52,71.2 105.41,66.55 100.58,66.55 | 111,73.48 P4ZD5.A | 100.58,66.55 100.58,73.07 arc-92 D6.A B2.- 98.81,77.47 D5.A | D8.A 111.93,74.84 111,73.48 | P4ZD2.A 91.23,73.1 91.19,72.64 91.18,72.64 Q2.2 | Q2.2 91.19,70.61 96.77,66.55 100.58,66.55 | OK1.3 73.91,64.97 74.17,63.5 82.3,63.5 82.3,58.17 84.07,57.15 95.5,57.15 95.5,66.55 91.18,70.1 Q2.2
CBIG
  Bottom 0.813: D3.A 97.28,69.6 D6.C 95,74.25 95,74.68 93.73,75.95 93.73,84.07 95.76,86.11 96.52,86.61 | R6.1 90.04,97.66 91.19,96.52 91.69,96.52 C6.P$2 91.95,88.65 AC3.P$1 95.5,87.63 96.52,86.61 | B2.~1 98.3,84.84 96.52,86.61
CSMALL  (1 unrouted)
  Bottom 0.406: R42.1 47.17,96.19 43.94,93.22 43.94,87.38 45.97,86.61 58.42,86.61 58.93,86.11
  Bottom 0.813: R25.1 44.07,104.14 R23.1 43.18,103.38 41.53,101.73 | 41.53,101.73 R22.P$2 38.27,98.47 U$3.1 | D7.A 54.1,81.53 56.9,85.09 57.66,85.09 58.67,86.11 58.93,86.11 63.5,86.11 65.02,87.63 65.02,88.87 B1.~2 70.71,89 | 70.71,89 C7.P$2 | 70.71,89 73.66,86.05 73.66,85.85 R9.1 | R42.2 43.3,99.96 41.53,101.73
D+  (via drill 0.6)  (2 unrouted)
  Top 0.406: R14.1 R12.1
  Top 0.813: 72.42,84.26 R11.1 70.87,80.77 arc113 74.68,69.34 R14.1 | 72.42,84.26 72.39,85.09 72.39,87.63 78.99,93.98 79.76,93.98 85.6,99.82 85.09,99.82 80.01,104.9 80.01,111.76 82.3,113.03 | 72.42,84.26 v71.63,84.84 73.66,84.84 73.66,83.06 78.49,83.06 +1+2.P$1
MI-
  Bottom 0.813: D8.C 107.44,88.48 107.44,89.41 87.88,108.97 MINUS_DC.P$1 71.12,111.51 62.74,103.12 62.74,96.61 D9.C
MINUS  (via drill 0.6)
  Top 0.406: R15.2 62.99,85.09 61.47,83.57 v61.72,75.44 | v49.02,51.31 43.32,50.43 R17.2 42.93,48.77 43.43,50.55 R8.2 | v84.33,73.15 88.67,73.13 +20+1.P$2 90.31,69.23 v88.9,63.75
  Bottom 0.406: C4.- 61.47,80.85 v61.72,75.44 60.45,77.22 60.45,71.63 58.17,70.36 58.17,65.02 54.36,63.25 | v49.02,51.31 54.36,53.85 | v88.9,63.75 Q2.3
  Bottom 0.813: 54.36,53.85 54.36,63.25 | v84.33,73.15 80.77,70.1 arc-54 69.85,70.1 60.45,71.63
  pour Bottom (isolate 0.813): 83.57,66.8 94.23,66.8 94.23,58.67 83.57,58.42
N$1
  Top 0.813: R18.1 R11.2 68.07,79.5 +1+3.P$1
N$2  (via drill 0.6)
  Top 0.406: +1+1.P$1 83.02,63.97 82.3,63.25 77.47,63.25 | v66.8,62.99 68.83,63.25 77.47,63.25 | v58.93,59.94 54.61,56.64 50.8,60.45 46.88,60.45 | 46.88,60.45 46.48,60.45 | R20.1 46.88,60.45 | 77.47,63.25 R12.2
  Bottom 0.406: v66.8,62.99 64.26,62.48 v58.93,59.94
N$3
  pour Top (isolate 0.813, hatched): 48.31,66.78 31.24,14.66 76.33,47.45 120.95,14.66 104.27,67.36 148.74,99.77 93.29,99.72 76.2,152.4 59.18,99.87 3.76,99.75
N$4
  Top 0.406: R19.1 72.39,68.85 +1.P$1
N$5
  Bottom 0.813: D7.C 55.37,71.12 56.39,70.1 56.39,68.56 R2.2
N$6
  Top 0.61: 8+.P$1 109.98,28.19 102.62,28.19 97.28,32 9+.P$2
N$7
  Top 0.406: +19.P$2 52.07,47.5 57.4,49.28 57.15,54.1 +20.P$1
N$8
  Top 0.406: +19.P$1 56.74,45.06 59.18,47.5 28+.P$2
N$9
  Top 0.406: 28+.P$1 74.93,46.48 64.01,43.94 27+.P$2
N$10
  Top 0.61: +20+1.P$1 29+1.P$2
N$11
  Top 0.61: 28+1.P$2 107.19,58.17 104.65,66.29 29+1.P$1
N$12
  Top 0.61: 7+.P$1 50.1,28.51 49.28,27.69 38.1,19.81 32.51,19.81 2+.P$2
N$13
  Top 0.406: 27+.P$1 65.02,39.12 54.86,33.27 47.5,32.51 47.5,30.99 47.75,30.99 48.01,30.48 7+.P$2
N$14
  Top 0.61: 2+.P$1 34.04,14.48 arc14 43.18,9.14 44.92,9.14 4+.P$2
N$15
  Top 0.61: 4+.P$1 48.77,7.11 arc19 58.17,4.57 59.22,4.57 6+.P$2
N$16
  Top 0.61: 6+.P$1 64.26,3.3 arc13 73.15,2.29 73.91,3.05 0+.P$2
N$17
  Top 0.61: 0+.P$1 79.76,2.03 arc13 88.14,3.05 88.39,4.57 5+.P$2
N$18
  Top 0.61: 5+.P$1 94.23,4.32 arc23 103.38,7.37 3+.P$2
N$19
  Top 0.61: 3+.P$1 arc16 118.11,14.73 1+.P$2
N$20
  Top 0.61: 1+.P$1 119.89,19.3 115.32,19.3 108.2,23.88 8+.P$2
N$21
  Top 0.61: 27+1.P$2 113.03,39.62 108.46,53.59 106.78,55.27 28+1.P$1
N$22
  Top 0.61: 4+1.P$2 146.05,50.29 arc-13 2+1.P$1
N$23
  Top 0.61: 9+.P$1 98.54,36.34 91.4,36.34 88.1,38.88 88.14,38.86 85.09,41.15 21+.P$2
N$24
  Top 0.61: 21+.P$1 97.24,37.54 22+.P$2
N$25
  Top 0.61: 22+.P$1 100.08,47.5 100.08,47.69 97.09,47.69 96.01,49.02 91.19,55.63 87.38,55.63 87.38,58.81 23+.P$2
N$26
  Top 0.61: 25+.P$2 62.48,56.13 69.34,56.13 71.12,61.98 77.47,61.98 24+.P$1
N$27
  Top 0.61: +1.P$2 67.06,68.58 arc86 63.5,61.72 25+.P$1
N$28
  Top 0.61: 23+.P$1 90.59,60.8 89.66,60.96 84.33,60.96 82.55,60.45 82.55,57.15 74.68,57.15 74.68,58.74 24+.P$2
N$29
  Top 0.61: 6+1.P$2 149.61,65.28 arc-22 4+1.P$1
N$30
  Top 0.61: 0+1.P$2 150.11,80.52 arc-15 6+1.P$1
N$31
  Top 0.61: 5+1.P$2 145.03,96.01 148.08,96.01 arc-15 149.86,85.6 0+1.P$1
N$32
  Top 0.61: 3+1.P$2 138.68,110.49 142.75,110.49 arc-10 147.07,99.31 5+1.P$1
N$33
  Top 0.61: 1+1.P$2 130.56,122.43 134.87,122.43 arc-21 140.97,113.28 3+1.P$1
N$34
  Top 0.406: 8+1.P$2 123.7,99.82 141.22,99.57
  Top 0.61: 141.22,99.57 arc25 125.22,125.48 128.78,129.03 131.32,126.24 131.83,125.73 1+1.P$1
N$35
  Top 0.406: 9+1.P$1 135.13,90.17 126.49,83.82 126.49,88.9 122.68,91.95 112.27,91.95 21+1.P$2
N$36
  Top 0.406: 21+1.P$1 22+1.P$2
N$37
  Top 0.406: 22+1.P$1 123.19,81.53 115.32,75.44 115.32,78.99 109.73,78.99 23+1.P$2
N$38
  Top 0.61: +1+1.P$2 80.77,70.87 arc31 83.06,74.93 84.07,76.45 86.36,76.45 86.61,76.71 86.61,77.47 25+1.P$1
N$39
  Top 0.61: 25+1.P$2 83.82,81.79 90.93,81.79 91.69,85.85 97.54,85.85 24+1.P$1
N$40
  Top 0.61: 24+1.P$2 99.06,73.15 112.27,73.15 112.78,73.66 23+1.P$1
N$41
  Top 0.61: 2+1.P$2 139.19,36.32 arc-19 7+1.P$1
N$42
  Top 0.61: 7+1.P$2 118.65,22.07 114.61,34.64 27+1.P$1
N$43
  Top 0.406: 8+1.P$1 9+1.P$2
N$44
  pour Top (isolate 0.813, hatched): 76.73,152.45 arc-78 150.27,90.47 arc-83 103.84,5.31 arc-84 9.42,40.97 arc-114 75.54,152.35 74.55,145.8 arc110 15.49,44.2 arc241 76.73,145.82
N$45  (via drill 0.6)
  Top 0.406: +20+3.P$2 40.89,43.6 40.89,45.21 42.53,46.85 R17.1 44.31,46.59 48.26,46.99 51.31,49.02 v52.58,49.78 | v66.8,65.53 70.61,65.79 71.37,65.02 72.02,65.02 R19.2 74.03,65.39 75.18,66.55 R14.2
  Bottom 0.406: 56.39,53.09 56.39,61.21 62.74,66.29 64.77,65.79 v66.8,65.53
  Bottom 0.813: v52.58,49.78 56.39,53.09
N$46
  Top 0.61: +19+2.P$2 69.34,89.92 +20+2.P$1
N$47
  Top 0.61: +19+2.P$1 76.2,103.12 74.68,105.16 28+2.P$2
N$48
  Top 0.61: 27+2.P$2 59.18,94.74 64.77,94.74 69.09,102.87 71.12,111.25 72.39,115.32 73.15,117.6 77.72,117.6 28+2.P$1
N$49
  Top 0.61: 4+2.P$2 33.02,128.27 arc-34 74.17,146.07 69.85,132.33 72.39,132.33 2+2.P$1
N$50
  Top 0.61: 4+2.P$1 34.54,137.41 arc-20 43.18,143 6+2.P$2
N$51
  Top 0.61: 6+2.P$1 49.28,145.03 arc-23 57.4,148.08 0+2.P$2
N$52
  Top 0.61: 0+2.P$1 64.52,149.35 arc-20 72.9,150.11 5+2.P$2
N$53
  Top 0.61: 5+2.P$1 78.99,149.1 79.5,149.86 arc-21 88.39,149.1 3+2.P$2
N$54
  Top 0.61: 3+2.P$1 94.49,148.34 arc-17 103.38,145.03 1+2.P$2
N$55
  Top 0.61: 1+2.P$1 109.73,142.24 arc-29 116.59,138.18 8+2.P$2
N$56
  Top 0.61: 21+2.P$2 84.69,125.99 81.92,134.17 9+2.P$1
N$57
  Top 0.61: 22+2.P$2 88.39,114.55 86.36,120.65 21+2.P$1
N$58
  Top 0.61: 23+2.P$2 92.65,101.33 89.82,110.06 22+2.P$1
N$59
  Top 0.61: +1+2.P$2 75.69,88.14 81.03,88.14 81.79,86.87 86.87,86.87 +2+2.P$1
N$60
  Top 0.61: +2+2.P$2 86.11,90.68 86.11,92.46 86.61,92.96 90.68,92.96 93.22,90.42 106.68,90.68 24+2.P$1
N$61
  Top 0.61: 23+2.P$1 94.68,99.67 102.75,99.67 24+2.P$2
N$62
  Top 0.61: 2+2.P$2 64.77,117.09 7+2.P$1
N$63
  Top 0.61: 7+2.P$2 63.5,113.03 60.2,101.85 62.23,98.04 27+2.P$1
N$64
  Top 0.61: 9+2.P$2 77.98,137.92 80.37,138.97 78.49,145.29 77.98,145.8 arc-37 117.35,132.08 120.4,133.86 8+2.P$1
N$65
  Top 0.406: +20+2.P$2 64.91,89.18 R15.1 64.49,87.26 R18.2
N$66
  Top 0.406: R8.1 45.21,55.49 +20.P$2 45.83,57.88 R20.2
N$67
  Top 0.406: 43.94,40.64 +20+3.P$1
  Top 0.61: +19+3.P$2 39.88,40.64 43.94,40.64
N$68
  Top 0.61: 28+3.P$2 23.88,22.86 28.7,18.8 32,21.84 33.78,21.84 35.56,27.69 39.12,27.69 +19+3.P$1
N$69
  Top 0.61: 27+3.P$2 arc14 18.54,29.72 23.37,29.72 28+3.P$1
N$70
  Top 0.61: 4+3.P$2 arc9 2.03,71.12 4.83,71.12 4.83,69.85 2+3.P$1
N$71
  Top 0.61: 6+3.P$2 arc14 2.79,87.12 5.08,86.61 4+3.P$1
N$72
  Top 0.61: 0+3.P$2 arc10 6.35,101.85 8.64,101.09 6+3.P$1
N$73
  Top 0.61: 0+3.P$1 14.73,115.57 12.95,115.57 arc-12 5+3.P$2
N$74
  Top 0.61: 5+3.P$1 26.16,121.41 arc21 13.46,99.57 17.78,99.57 18.78,98.82 18.54,98.81 18.78,98.03 3+3.P$2
N$75
  Top 0.61: 1+3.P$2 3+3.P$1
N$76
  Top 0.61: 8+3.P$2 33.78,77.47 25.4,84.07 25.4,87.12 1+3.P$1
N$77
  Top 0.61: 21+3.P$2 31.69,96.84 31.75,96.77 34.04,92.71 39.88,91.95 43.18,90.42 9+3.P$1
N$78
  Top 0.61: 21+3.P$1 38.1,99.57 42.93,99.57 22+3.P$2
N$79
  Top 0.61: 23+3.P$2 22+3.P$1
N$80
  Top 0.61: +1+3.P$2 64.77,72.64 +2+3.P$1
N$81
  Top 0.61: +3+3.P$1 +2+3.P$2
N$82
  Top 0.61: +3+3.P$2 49.28,75.18 57.4,78.99 23+3.P$1
N$83
  Top 0.61: 2+3.P$2 arc22 4.83,56.39 7.62,56.39 7.87,55.12 7+3.P$1
N$84
  Top 0.61: 7+3.P$2 arc23 10.41,42.42 13.97,42.42 27+3.P$1
N$85
  Top 0.61: 9+3.P$2 39.62,80.26 8+3.P$1
N$86  (via drill 0.6)  (3 unrouted)
  Top 0.406: v86.87,50.29 88.65,50.29 93.22,45.72 94.23,43.43 v95.25,41.66
  Bottom 0.406: U$2.6 86.61,50.04 v86.87,50.29 86.87,53.09 87.38,53.59 | v95.25,41.66 93.73,42.93 U$1.P$8 | 80.52,60.71 80.52,55.88 82.55,53.85
  Bottom 0.813: R2.1 68.2,68.2 69.6,66.8 69.6,63.25 70.1,61.72 78.49,61.72 80.52,60.71 | P4ZD1.C v95.25,41.66 C5.2 R21.2
N$87
  Bottom 0.813: OK1.1 76.71,56.7 76.71,54.1 76.2,53.59 R4.1
N$88
  Bottom 0.406: U$1.P$5 100.36,50.29 R1.1 101.22,54.48 103.12,56.39 103.12,58.83 PH1.2 107.61,59.69 R36.S
  Bottom 0.813: U$2.1 88.65,49.02 90.42,50.8 U$1.P$5
N$89
  Bottom 0.813: R5.1 R6.2
N$90
  Bottom 0.813: R9.2 R7.1
N$91
  Bottom 0.813: D4.C B2.+ | D3.C D4.C | D4.C 107.02,77.81 109.73,77.98 109.98,96.63 R16.P$1 107.32,99.29 R32.2 107.44,101.72 107.44,102.87 104.9,105.41 R30.2
N$92
  Bottom 0.813: D2.A 44.93,64.64 R3.2
N$94
  Bottom 0.813: OK1.4 arc82 Q2.1 86.82,71.66 P4ZD2.C 87.27,75.89 R13.2
N$95
  Bottom 0.406: 75.69,40.64 75.44,41.66 75.44,47.75 75.95,48.26 75.95,49.38 R4.2
  Bottom 0.813: U$2.4 86.36,44.45 86.36,41.15 80.77,41.15 75.69,40.64 | U$1.P$3 78.74,48.26 76.96,49.38 R4.2
N$96  (2 unrouted)
N$97  (1 unrouted)
N$98
  Bottom 0.406: PLUS_DC.P$1 65.02,117.48 R28.2
  Bottom 0.813: D1.A 65.02,117.48
N$99
  Bottom 0.813: R26.1 48.89,106.17 R23.2
N$100
  Bottom 0.813: R27.1 47.5,110.24 46.23,109.6 R25.2
N$101  (1 unrouted)
  Bottom 0.813: R39.1 R38.1 50.36,95.7 R10.P$2 50.8,92.71 R41.1 | R3.1 51.08,70.94 C9.+ 51.51,77.26 C2.+ 50.8,82.55 R41.2
N$102  (1 unrouted)
  Bottom 0.406: 80.01,38.23 74.42,39.12 74.42,46.99 73.66,47.75 73.66,51.05 80.77,51.05
  Bottom 0.813: 80.01,38.23 86.42,38.42 87.88,38.86 | 80.77,51.05 81.03,50.8 U$1.P$4 | U$2.3 88.9,44.45 88.9,39.88 87.88,38.86 | 87.88,38.86 C8.2
N$103
  Bottom 0.813: P4ZD6.A P4ZD5.C
N$104
  Bottom 0.813: R29.1 37.95,86.03 P4ZD7.C 36.75,88.2 U$3.3
N$105
  Bottom 0.813: P4ZD6.C P4ZD4.A
N$106  (1 unrouted)
N$107
  Bottom 0.813: R31.2 R30.1
N$108
  Bottom 0.813: R33.2 R32.1
N$109
  Bottom 0.406: B1.+ 59.79,89 60.71,89.92 59.94,94.36 R34.2
  Bottom 0.813: R10.P$1 60.39,105.47 R37.2 R34.2
N$110
  Bottom 0.813: R38.2 55.5,98.81 55.88,99.31 56.9,100.58 R34.1
N$111
  Bottom 0.813: R37.1 54.73,102.62 R39.2
N$112  (1 unrouted)
N$113  (1 unrouted)
N$114  (1 unrouted)
N$115
  Bottom 0.406: Q6.C 109.98,116.33 110.4,116.75 C10.C 111.42,119.13 L1.1
N$116
  Bottom 0.406: VR16.1 118.07,106.02 VC12.1 115.76,107 115.32,107.44 115.32,109.73 116.59,111 117.86,111 118.62,111.76 118.62,112.74 L2.1 118.58,114.01 120.4,115.82 120.4,121.41 120.14,121.67 108.46,121.67 108.2,121.41 108.2,116.84 105.92,114.55 104.71,114.55 VC11.2 104.58,114.55 103.38,114.55 98.81,119.13 OK2.3
N$117  (2 unrouted)
N$118  (1 unrouted)
PLUS5  (via drill 0.6)  (9 unrouted)
  Top 0.813: v68.07,75.44 69.34,74.17
  Bottom 0.406: 43.51,97.23 47.08,100.74 | R16.P$2 98.06,109.72 99.57,108.2 100.58,108.2 100.84,107.95 105.92,107.95 106.43,108.46
  Bottom 0.813: R16.P$2 96.89,105.66 R31.1 96.64,104.78 98.81,102.62 98.81,102.23 R33.1 | R22.P$1 51.5,112.33 R27.2 R26.2 52.1,109.7 54.07,107.73 | 43.51,97.23 42.58,95.18 42.58,93.47 | R29.2 42.58,85.84 42.58,93.47 | 42.58,93.47 U$3.2 | v68.07,75.44 C4.+ | D1.C 55.45,110.32 55.45,109.1 54.07,107.73 | 47.08,100.74 54.07,107.73
VDD  (3 unrouted)
  Bottom 0.406: R35.S 69.6,43.69 70.87,44.96 72.39,44.96 | 77.22,44.7 78.23,45.72 U$1.P$2 84.84,45.72 | 84.84,45.72 U$2.5 | PH1.1 97.12,55.97 93.73,55.88 85.09,55.88 85.09,45.97 84.84,45.72
  Bottom 0.813: R35.S 57.66,40.13 56.13,42.16 51.56,42.16 C1.2 44.96,50.03 46.23,51.31 47.07,53.67 C3.+ 50.37,61.13 49.53,61.98 41.4,61.98 38.61,64.77 36.32,65.45 D2.C 39.07,72.23 P4ZD3.C | PH1.1 100.42,63.25 104.14,63.25 106.68,62.99 110.92,67.23 R36.E
VSS  (4 unrouted)
  Bottom 0.406: U$1.P$7 U$2.2 | 54.1,88.14 53.59,87.63 52.58,87.63 52.32,87.38 47.24,87.38 46.23,88.39 | R1.2 101.22,45.85 101.09,45.72
  Bottom 0.813: 49.28,39.12 46.1,42.29 C1.1 41.02,49.4 38.86,51.56 | 49.28,39.12 arc53 92.2,32.51 92.55,32.73 | 38.86,51.56 arc-56 31.75,79.4 33.81,79.67 | C3.- 41.15,57.15 39.12,55.12 38.86,55.12 37.59,53.85 37.59,53.34 38.86,52.07 38.86,51.56 | 33.81,79.67 P4ZD7.A | U$1.P$7 101.09,45.72 109.47,45.72 109.73,45.47 109.73,44.96 109.47,44.7 | 109.47,44.7 105.92,41.15 92.55,32.73 | OK1.2 71.88,58.22 71.88,50.29 69.09,47.5 54.86,47.5 R46.1 | 44.2,78.23 39.88,78.23 35.18,78.11 | 44.2,78.23 45.72,78.23 C2.- 45.51,77.77 C9.- | 35.18,78.11 34.07,77.69 33.81,79.67 | D9.A 57.24,95.08 57.15,92.96 57.15,91.98 B1.- 55.53,91.6 54.1,90.17 54.1,88.14 | 35.18,78.11 P4ZD3.A | R21.1 C8.1 | 92.55,32.73 R21.1 | R21.1 C5.1 P4ZD1.A | 109.47,44.7 R36.A | 49.28,39.12 53.59,39.62 | 44.2,78.23 R43.2
(copper drawn outside any net)
  shapes: Bottom circle x3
